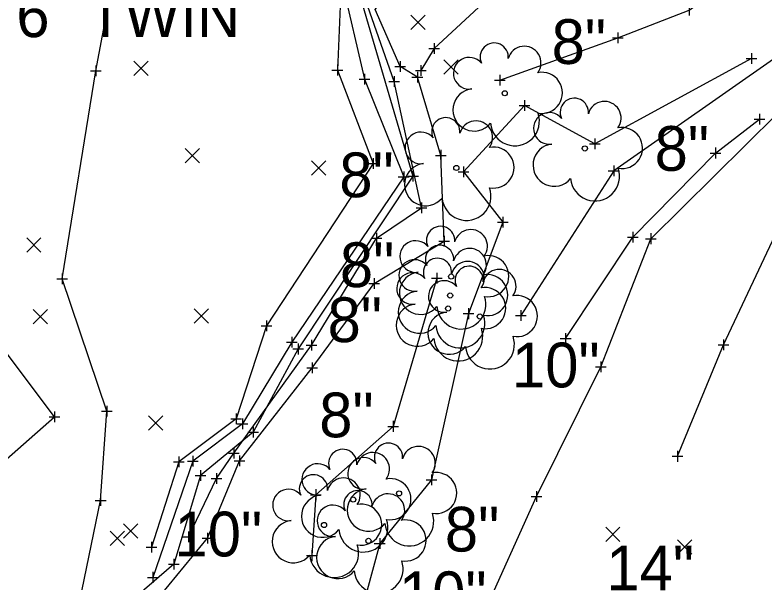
# Model space of a CAD drawing. Extents: x 2005176 to 2005823, y 572472 to 572942.
# Drawn here: x 2005494.7 to 2005564.6, y 572498.2 to 572551.1 of the extents above; entities that cross this region are included whole.
import ezdxf

# ---------------------------------------------------------------- set-up
doc = ezdxf.new("R2010")
doc.units = 0
for name, color, linetype in [('GE_X_Alignment_100_Stations', 7, 'Continuous'), ('GE_X_Alignment_500_Bearings', 7, 'Continuous'), ('GE_X_Alignment_500_Cardinal_Points', 7, 'Continuous'), ('SV_P_Mon_Cells_Set', 7, 'Continuous'), ('SV_X_Random_Point', 7, 'Continuous'), ('SV_X_Shot_Marker', 7, 'Continuous'), ('VG_X_Text', 7, 'Continuous')]:
    doc.layers.add(name, color=color, linetype=linetype)

msp = doc.modelspace()

# ---------------------------------------------------------------- linework, layer by layer
at = {"layer": 'GE_X_Alignment_100_Stations'}
msp.add_lwpolyline([(2005526.126, 572569.752), (2005528.014, 572562.539), (2005526.605, 572553.625), (2005531.765, 572536.046), (2005521.073, 572519.95), (2005516.881, 572512.197), (2005511.963, 572508.178), (2005509.477, 572499.914), (2005500.59, 572492.24)], dxfattribs=at)
at = {"layer": 'GE_X_Alignment_500_Bearings'}
for points in [[(2005539.868, 572544.991), (2005550.848, 572548.934), (2005557.502, 572551.51), (2005560.928, 572553.964), (2005549.485, 572559.497), (2005546.556, 572569.14), (2005548.532, 572572.172)], [(2005544.658, 572568.151), (2005544.953, 572560.493), (2005539.957, 572553.713), (2005533.75, 572547.927), (2005532.487, 572545.893)], [(2005500.74, 572496.501), (2005502.666, 572505.833), (2005503.248, 572514.147), (2005499.084, 572526.483), (2005502.215, 572545.864), (2005503.875, 572554.617), (2005506.82, 572561.115), (2005509.657, 572562.142), (2005510.083, 572567.796)], [(2005510.836, 572502.456), (2005513.462, 572507.883), (2005515.078, 572510.249), (2005522.31, 572520.302), (2005528.373, 572530.257), (2005532.552, 572533.09), (2005530.012, 572544.855), (2005527.353, 572552.501), (2005529.477, 572556.747)], [(2005525.157, 572554.054), (2005527.24, 572545.068), (2005530.901, 572535.974), (2005520.467, 572520.575), (2005515.869, 572512.981), (2005511.264, 572509.493), (2005507.53, 572498.68)], [(2005565.964, 572547.382), (2005550.466, 572536.529), (2005541.813, 572523.069)], [(2005532.268, 572476.648), (2005533.838, 572485.174), (2005538.205, 572494.974), (2005543.28, 572506.202), (2005549.269, 572518.298), (2005553.939, 572530.22), (2005565.743, 572541.873), (2005569.086, 572544.678)], [(2005545.99, 572520.929), (2005552.251, 572530.355), (2005559.963, 572538.2), (2005564.062, 572541.354)], [(2005533.98, 572526.541), (2005529.917, 572512.744), (2005522.716, 572506.378), (2005522.338, 572500.703)], [(2005488.988, 572499.456), (2005492.028, 572508.058), (2005498.368, 572513.628), (2005493.781, 572519.739)]]:
    msp.add_lwpolyline(points, dxfattribs=at)
at = {"layer": 'GE_X_Alignment_500_Cardinal_Points'}
for points in [[(2005525.242, 572557.882), (2005524.719, 572545.929), (2005528.063, 572537.211), (2005518.106, 572522.096), (2005515.293, 572513.45), (2005509.953, 572509.45), (2005507.414, 572501.497)], [(2005505.489, 572493.647), (2005512.611, 572502.332), (2005515.602, 572509.525), (2005522.377, 572518.182), (2005528.142, 572526.059), (2005534.669, 572529.98), (2005534.351, 572537.981), (2005532.172, 572545.253), (2005530.581, 572546.261), (2005528.258, 572551.573), (2005532.711, 572557)], [(2005563.298, 572546.993), (2005548.706, 572539.064), (2005542.148, 572542.622), (2005536.485, 572536.442), (2005540.134, 572531.756), (2005536.945, 572523.241), (2005533.482, 572507.768), (2005528.663, 572501.824), (2005525.549, 572490.297), (2005521.368, 572479.609)], [(2005556.423, 572509.951), (2005560.699, 572520.328), (2005567.526, 572534.832), (2005575.107, 572545.623)]]:
    msp.add_lwpolyline(points, dxfattribs=at)
at = {"layer": 'SV_P_Mon_Cells_Set'}
for p, q in [((2005557.502, 572552.01), (2005557.502, 572551.01)), ((2005550.848, 572549.434), (2005550.848, 572548.434)), ((2005550.348, 572548.934), (2005551.348, 572548.934)), ((2005550.848, 572548.934), (2005550.848, 572548.934)), ((2005533.25, 572547.927), (2005534.25, 572547.927)), ((2005533.75, 572548.427), (2005533.75, 572547.427)), ((2005533.75, 572547.927), (2005533.75, 572547.927)), ((2005563.298, 572547.493), (2005563.298, 572546.493)), ((2005502.215, 572546.364), (2005502.215, 572545.364)), ((2005524.719, 572546.429), (2005524.719, 572545.429)), ((2005530.581, 572546.761), (2005530.581, 572545.761)), ((2005532.487, 572546.393), (2005532.487, 572545.393)), ((2005562.798, 572546.993), (2005563.798, 572546.993)), ((2005563.298, 572546.993), (2005563.298, 572546.993)), ((2005501.715, 572545.864), (2005502.715, 572545.864)), ((2005502.215, 572545.864), (2005502.215, 572545.864)), ((2005524.219, 572545.929), (2005525.219, 572545.929)), ((2005524.719, 572545.929), (2005524.719, 572545.929)), ((2005530.081, 572546.261), (2005531.081, 572546.261)), ((2005530.581, 572546.261), (2005530.581, 572546.261)), ((2005531.987, 572545.893), (2005532.987, 572545.893)), ((2005532.172, 572545.753), (2005532.172, 572544.753)), ((2005532.487, 572545.893), (2005532.487, 572545.893)), ((2005526.74, 572545.068), (2005527.74, 572545.068)), ((2005527.24, 572545.568), (2005527.24, 572544.568)), ((2005527.24, 572545.068), (2005527.24, 572545.068)), ((2005530.012, 572545.355), (2005530.012, 572544.355)), ((2005531.672, 572545.253), (2005532.672, 572545.253)), ((2005532.172, 572545.253), (2005532.172, 572545.253)), ((2005539.368, 572544.991), (2005540.368, 572544.991)), ((2005539.868, 572545.491), (2005539.868, 572544.491)), ((2005539.868, 572544.991), (2005539.868, 572544.991)), ((2005529.512, 572544.855), (2005530.512, 572544.855)), ((2005530.012, 572544.855), (2005530.012, 572544.855)), ((2005542.148, 572543.122), (2005542.148, 572542.122)), ((2005541.648, 572542.622), (2005542.648, 572542.622)), ((2005542.148, 572542.622), (2005542.148, 572542.622)), ((2005564.062, 572541.854), (2005564.062, 572540.854)), ((2005563.562, 572541.354), (2005564.562, 572541.354)), ((2005564.062, 572541.354), (2005564.062, 572541.354)), ((2005548.706, 572539.564), (2005548.706, 572538.564)), ((2005548.206, 572539.064), (2005549.206, 572539.064)), ((2005548.706, 572539.064), (2005548.706, 572539.064)), ((2005559.963, 572538.7), (2005559.963, 572537.7)), ((2005533.851, 572537.981), (2005534.851, 572537.981)), ((2005534.351, 572538.481), (2005534.351, 572537.481)), ((2005534.351, 572537.981), (2005534.351, 572537.981)), ((2005559.463, 572538.2), (2005560.463, 572538.2)), ((2005559.963, 572538.2), (2005559.963, 572538.2)), ((2005528.063, 572537.711), (2005528.063, 572536.711)), ((2005527.563, 572537.211), (2005528.563, 572537.211)), ((2005528.063, 572537.211), (2005528.063, 572537.211)), ((2005536.485, 572536.942), (2005536.485, 572535.942)), ((2005550.466, 572537.029), (2005550.466, 572536.029)), ((2005530.401, 572535.974), (2005531.401, 572535.974)), ((2005530.901, 572536.474), (2005530.901, 572535.474)), ((2005530.901, 572535.974), (2005530.901, 572535.974)), ((2005531.265, 572536.046), (2005532.265, 572536.046)), ((2005531.765, 572536.546), (2005531.765, 572535.546)), ((2005531.765, 572536.046), (2005531.765, 572536.046)), ((2005535.985, 572536.442), (2005536.985, 572536.442)), ((2005536.485, 572536.442), (2005536.485, 572536.442)), ((2005549.966, 572536.529), (2005550.966, 572536.529)), ((2005550.466, 572536.529), (2005550.466, 572536.529)), ((2005532.052, 572533.09), (2005533.052, 572533.09)), ((2005532.552, 572533.59), (2005532.552, 572532.59)), ((2005532.552, 572533.09), (2005532.552, 572533.09)), ((2005539.634, 572531.756), (2005540.634, 572531.756)), ((2005540.134, 572532.256), (2005540.134, 572531.256)), ((2005540.134, 572531.756), (2005540.134, 572531.756)), ((2005528.373, 572530.757), (2005528.373, 572529.757)), ((2005534.669, 572530.48), (2005534.669, 572529.48)), ((2005551.751, 572530.355), (2005552.751, 572530.355)), ((2005552.251, 572530.855), (2005552.251, 572529.855)), ((2005552.251, 572530.355), (2005552.251, 572530.355)), ((2005553.939, 572530.72), (2005553.939, 572529.72)), ((2005527.873, 572530.257), (2005528.873, 572530.257)), ((2005528.373, 572530.257), (2005528.373, 572530.257)), ((2005534.169, 572529.98), (2005535.169, 572529.98)), ((2005534.669, 572529.98), (2005534.669, 572529.98)), ((2005553.439, 572530.22), (2005554.439, 572530.22)), ((2005553.939, 572530.22), (2005553.939, 572530.22)), ((2005499.084, 572526.983), (2005499.084, 572525.983)), ((2005533.98, 572527.041), (2005533.98, 572526.041)), ((2005498.584, 572526.483), (2005499.584, 572526.483)), ((2005499.084, 572526.483), (2005499.084, 572526.483)), ((2005528.142, 572526.559), (2005528.142, 572525.559)), ((2005533.48, 572526.541), (2005534.48, 572526.541)), ((2005533.98, 572526.541), (2005533.98, 572526.541)), ((2005527.642, 572526.059), (2005528.642, 572526.059)), ((2005528.142, 572526.059), (2005528.142, 572526.059)), ((2005536.945, 572523.741), (2005536.945, 572522.741)), ((2005541.813, 572523.569), (2005541.813, 572522.569)), ((2005536.445, 572523.241), (2005537.445, 572523.241)), ((2005536.945, 572523.241), (2005536.945, 572523.241)), ((2005541.313, 572523.069), (2005542.313, 572523.069)), ((2005541.813, 572523.069), (2005541.813, 572523.069)), ((2005517.606, 572522.096), (2005518.606, 572522.096)), ((2005518.106, 572522.596), (2005518.106, 572521.596)), ((2005518.106, 572522.096), (2005518.106, 572522.096)), ((2005545.99, 572521.429), (2005545.99, 572520.429)), ((2005519.967, 572520.575), (2005520.967, 572520.575)), ((2005520.467, 572521.075), (2005520.467, 572520.075)), ((2005520.467, 572520.575), (2005520.467, 572520.575)), ((2005522.31, 572520.802), (2005522.31, 572519.802)), ((2005545.49, 572520.929), (2005546.49, 572520.929)), ((2005545.99, 572520.929), (2005545.99, 572520.929)), ((2005560.699, 572520.828), (2005560.699, 572519.828)), ((2005520.573, 572519.95), (2005521.573, 572519.95)), ((2005521.073, 572520.45), (2005521.073, 572519.45)), ((2005521.073, 572519.95), (2005521.073, 572519.95)), ((2005521.81, 572520.302), (2005522.81, 572520.302)), ((2005522.31, 572520.302), (2005522.31, 572520.302)), ((2005560.199, 572520.328), (2005561.199, 572520.328)), ((2005560.699, 572520.328), (2005560.699, 572520.328)), ((2005522.377, 572518.682), (2005522.377, 572517.682)), ((2005549.269, 572518.798), (2005549.269, 572517.798)), ((2005521.877, 572518.182), (2005522.877, 572518.182)), ((2005522.377, 572518.182), (2005522.377, 572518.182)), ((2005548.769, 572518.298), (2005549.769, 572518.298)), ((2005549.269, 572518.298), (2005549.269, 572518.298)), ((2005503.248, 572514.647), (2005503.248, 572513.647)), ((2005497.868, 572513.628), (2005498.868, 572513.628)), ((2005498.368, 572514.128), (2005498.368, 572513.128)), ((2005498.368, 572513.628), (2005498.368, 572513.628)), ((2005502.748, 572514.147), (2005503.748, 572514.147)), ((2005503.248, 572514.147), (2005503.248, 572514.147)), ((2005515.293, 572513.95), (2005515.293, 572512.95)), ((2005514.793, 572513.45), (2005515.793, 572513.45)), ((2005515.293, 572513.45), (2005515.293, 572513.45)), ((2005515.369, 572512.981), (2005516.369, 572512.981)), ((2005515.869, 572513.481), (2005515.869, 572512.481)), ((2005515.869, 572512.981), (2005515.869, 572512.981)), ((2005529.917, 572513.244), (2005529.917, 572512.244)), ((2005516.381, 572512.197), (2005517.381, 572512.197)), ((2005516.881, 572512.697), (2005516.881, 572511.697)), ((2005516.881, 572512.197), (2005516.881, 572512.197)), ((2005529.417, 572512.744), (2005530.417, 572512.744)), ((2005529.917, 572512.744), (2005529.917, 572512.744)), ((2005515.078, 572510.749), (2005515.078, 572509.749)), ((2005514.578, 572510.249), (2005515.578, 572510.249)), ((2005515.078, 572510.249), (2005515.078, 572510.249)), ((2005515.602, 572510.025), (2005515.602, 572509.025)), ((2005556.423, 572510.451), (2005556.423, 572509.451)), ((2005509.453, 572509.45), (2005510.453, 572509.45)), ((2005509.953, 572509.95), (2005509.953, 572508.95)), ((2005509.953, 572509.45), (2005509.953, 572509.45)), ((2005510.764, 572509.493), (2005511.764, 572509.493)), ((2005511.264, 572509.993), (2005511.264, 572508.993)), ((2005511.264, 572509.493), (2005511.264, 572509.493)), ((2005515.102, 572509.525), (2005516.102, 572509.525)), ((2005515.602, 572509.525), (2005515.602, 572509.525)), ((2005555.923, 572509.951), (2005556.923, 572509.951)), ((2005556.423, 572509.951), (2005556.423, 572509.951)), ((2005511.963, 572508.678), (2005511.963, 572507.678)), ((2005511.463, 572508.178), (2005512.463, 572508.178)), ((2005511.963, 572508.178), (2005511.963, 572508.178)), ((2005513.462, 572508.383), (2005513.462, 572507.383)), ((2005533.482, 572508.268), (2005533.482, 572507.268)), ((2005512.962, 572507.883), (2005513.962, 572507.883)), ((2005513.462, 572507.883), (2005513.462, 572507.883)), ((2005532.982, 572507.768), (2005533.982, 572507.768)), ((2005533.482, 572507.768), (2005533.482, 572507.768)), ((2005522.716, 572506.878), (2005522.716, 572505.878)), ((2005543.28, 572506.702), (2005543.28, 572505.702)), ((2005502.166, 572505.833), (2005503.166, 572505.833)), ((2005502.666, 572506.333), (2005502.666, 572505.333)), ((2005502.666, 572505.833), (2005502.666, 572505.833)), ((2005522.216, 572506.378), (2005523.216, 572506.378)), ((2005522.716, 572506.378), (2005522.716, 572506.378)), ((2005542.78, 572506.202), (2005543.78, 572506.202)), ((2005543.28, 572506.202), (2005543.28, 572506.202)), ((2005510.336, 572502.456), (2005511.336, 572502.456)), ((2005510.836, 572502.956), (2005510.836, 572501.956)), ((2005510.836, 572502.456), (2005510.836, 572502.456)), ((2005512.611, 572502.832), (2005512.611, 572501.832)), ((2005507.414, 572501.997), (2005507.414, 572500.997)), ((2005512.111, 572502.332), (2005513.111, 572502.332)), ((2005512.611, 572502.332), (2005512.611, 572502.332)), ((2005528.163, 572501.824), (2005529.163, 572501.824)), ((2005528.663, 572502.324), (2005528.663, 572501.324)), ((2005528.663, 572501.824), (2005528.663, 572501.824)), ((2005506.914, 572501.497), (2005507.914, 572501.497)), ((2005507.414, 572501.497), (2005507.414, 572501.497)), ((2005522.338, 572501.203), (2005522.338, 572500.203)), ((2005509.477, 572500.414), (2005509.477, 572499.414)), ((2005521.838, 572500.703), (2005522.838, 572500.703)), ((2005522.338, 572500.703), (2005522.338, 572500.703)), ((2005508.977, 572499.914), (2005509.977, 572499.914)), ((2005509.477, 572499.914), (2005509.477, 572499.914)), ((2005507.53, 572499.18), (2005507.53, 572498.18)), ((2005507.03, 572498.68), (2005508.03, 572498.68)), ((2005507.53, 572498.68), (2005507.53, 572498.68))]:
    msp.add_line(p, q, dxfattribs=at)
at = {"layer": 'SV_X_Random_Point'}
for p, q in [((2005531.554, 572549.697), (2005532.888, 572551.032)), ((2005531.554, 572551.032), (2005532.888, 572549.697)), ((2005505.75, 572545.412), (2005507.084, 572546.747)), ((2005505.75, 572546.747), (2005507.084, 572545.412)), ((2005534.639, 572545.555), (2005535.973, 572546.89)), ((2005534.639, 572546.89), (2005535.973, 572545.555)), ((2005510.553, 572537.278), (2005511.887, 572538.613)), ((2005510.553, 572538.613), (2005511.887, 572537.278)), ((2005522.31, 572536.124), (2005523.644, 572537.459)), ((2005522.31, 572537.459), (2005523.644, 572536.124)), ((2005495.775, 572528.955), (2005497.108, 572530.29)), ((2005495.775, 572530.29), (2005497.108, 572528.955)), ((2005496.373, 572522.3), (2005497.706, 572523.635)), ((2005496.373, 572523.635), (2005497.706, 572522.3)), ((2005511.385, 572522.358), (2005512.718, 572523.693)), ((2005511.385, 572523.693), (2005512.718, 572522.358)), ((2005507.114, 572512.397), (2005508.447, 572513.732)), ((2005507.114, 572513.732), (2005508.447, 572512.397)), ((2005504.783, 572502.334), (2005506.116, 572503.669)), ((2005504.783, 572503.669), (2005506.116, 572502.334)), ((2005549.719, 572502.008), (2005551.052, 572503.343)), ((2005549.719, 572503.343), (2005551.052, 572502.008)), ((2005503.542, 572501.645), (2005504.875, 572502.98)), ((2005503.542, 572502.98), (2005504.875, 572501.645)), ((2005556.418, 572500.836), (2005557.751, 572502.171)), ((2005556.418, 572502.171), (2005557.751, 572500.836))]:
    msp.add_line(p, q, dxfattribs=at)
at = {"layer": 'SV_X_Shot_Marker'}
for centre in [(2005540.316, 572543.766), (2005547.779, 572538.625), (2005535.808, 572536.81), (2005535.324, 572526.693), (2005535.227, 572524.93), (2005535.034, 572523.718), (2005537.987, 572522.974), (2005530.469, 572506.497), (2005526.201, 572505.926), (2005523.476, 572503.554), (2005527.618, 572502.078)]:
    msp.add_circle(centre, 0.24, dxfattribs=at)
for centre, radius, start, end in [((2005539.332, 572547.134), 1.317, 354.0047, 205.97412), ((2005542.142, 572546.595), 1.553, 323.82996, 165.0376), ((2005537.006, 572545.63), 1.471, 39.06254, 279.54124), ((2005543.776, 572543.802), 1.915, 259.14531, 101.45961), ((2005537.462, 572542.218), 1.974, 96.17219, 320.57371), ((2005546.796, 572541.992), 1.317, 354.0047, 205.97412), ((2005549.606, 572541.454), 1.553, 323.82996, 165.0376), ((2005534.824, 572540.177), 1.317, 354.0047, 205.97412), ((2005541.262, 572541.161), 2.284, 184.94757, 19.45715), ((2005544.47, 572540.489), 1.471, 39.06254, 279.54124), ((2005537.634, 572539.639), 1.553, 323.82996, 165.0376), ((2005532.498, 572538.674), 1.471, 39.06254, 279.54124), ((2005551.24, 572538.66), 1.915, 259.14531, 101.45961), ((2005539.268, 572536.846), 1.915, 259.14531, 101.45961), ((2005544.926, 572537.076), 1.974, 96.17219, 320.57371), ((2005532.954, 572535.261), 1.974, 96.17219, 320.57371), ((2005548.726, 572536.019), 2.284, 184.94757, 19.45715), ((2005536.754, 572534.205), 2.284, 184.94757, 19.45715), ((2005534.34, 572530.06), 1.317, 354.0047, 205.97412), ((2005537.15, 572529.522), 1.553, 323.82996, 165.0376), ((2005532.015, 572528.557), 1.471, 39.06254, 279.54124), ((2005534.244, 572528.297), 1.317, 354.0047, 205.97412), ((2005537.053, 572527.759), 1.553, 323.82996, 165.0376), ((2005531.918, 572526.794), 1.471, 39.06254, 279.54124), ((2005534.05, 572527.085), 1.317, 354.0047, 205.97412), ((2005538.784, 572526.729), 1.915, 259.14531, 101.45961), ((2005536.86, 572526.547), 1.553, 323.82996, 165.0376), ((2005537.003, 572526.341), 1.317, 354.0047, 205.97412), ((2005531.725, 572525.582), 1.471, 39.06254, 279.54124), ((2005532.471, 572525.144), 1.974, 96.17219, 320.57371), ((2005538.688, 572524.966), 1.915, 259.14531, 101.45961), ((2005539.813, 572525.803), 1.553, 323.82996, 165.0376), ((2005534.678, 572524.838), 1.471, 39.06254, 279.54124), ((2005538.494, 572523.754), 1.915, 259.14531, 101.45961), ((2005532.374, 572523.381), 1.974, 96.17219, 320.57371), ((2005536.27, 572524.088), 2.284, 184.94757, 19.45715), ((2005541.447, 572523.01), 1.915, 259.14531, 101.45961), ((2005532.181, 572522.169), 1.974, 96.17219, 320.57371), ((2005535.134, 572521.425), 1.974, 96.17219, 320.57371), ((2005536.174, 572522.325), 2.284, 184.94757, 19.45715), ((2005535.981, 572521.113), 2.284, 184.94757, 19.45715), ((2005538.933, 572520.368), 2.284, 184.94757, 19.45715), ((2005529.486, 572509.865), 1.317, 354.0047, 205.97412), ((2005532.296, 572509.326), 1.553, 323.82996, 165.0376), ((2005525.218, 572509.293), 1.317, 354.0047, 205.97412), ((2005528.027, 572508.755), 1.553, 323.82996, 165.0376), ((2005527.16, 572508.361), 1.471, 39.06254, 279.54124), ((2005522.892, 572507.79), 1.471, 39.06254, 279.54124), ((2005522.492, 572506.921), 1.317, 354.0047, 205.97412), ((2005525.302, 572506.383), 1.553, 323.82996, 165.0376), ((2005533.93, 572506.533), 1.915, 259.14531, 101.45961), ((2005529.662, 572505.962), 1.915, 259.14531, 101.45961), ((2005520.166, 572505.418), 1.471, 39.06254, 279.54124), ((2005526.634, 572505.446), 1.317, 354.0047, 205.97412), ((2005527.616, 572504.949), 1.974, 96.17219, 320.57371), ((2005523.348, 572504.377), 1.974, 96.17219, 320.57371), ((2005529.444, 572504.907), 1.553, 323.82996, 165.0376), ((2005524.308, 572503.942), 1.471, 39.06254, 279.54124), ((2005526.936, 572503.589), 1.915, 259.14531, 101.45961), ((2005531.416, 572503.892), 2.284, 184.94757, 19.45715), ((2005520.622, 572502.005), 1.974, 96.17219, 320.57371), ((2005527.148, 572503.32), 2.284, 184.94757, 19.45715), ((2005531.078, 572502.114), 1.915, 259.14531, 101.45961), ((2005524.764, 572500.53), 1.974, 96.17219, 320.57371), ((2005524.422, 572500.948), 2.284, 184.94757, 19.45715), ((2005528.564, 572499.473), 2.284, 184.94757, 19.45715)]:
    msp.add_arc(centre, radius, start, end, dxfattribs=at)

# ---------------------------------------------------------------- texts
at = {"layer": 'VG_X_Text'}
for s, p in [('6" TWIN', (2005494.808, 572548.992)), ('8"', (2005544.681, 572546.492)), ('8"', (2005554.277, 572536.541)), ('8"', (2005524.902, 572534.082)), ('8"', (2005524.955, 572525.71)), ('8"', (2005523.808, 572520.588)), ('10"', (2005540.986, 572516.371)), ('8"', (2005523.03, 572511.721)), ('8"', (2005534.733, 572501.084)), ('10"', (2005509.541, 572500.629)), ('14"', (2005549.78, 572497.471)), ('10"', (2005530.453, 572495.063))]:
    msp.add_text(s, height=4.1667, dxfattribs=at).set_placement(p)

doc.saveas('drawing.dxf')
